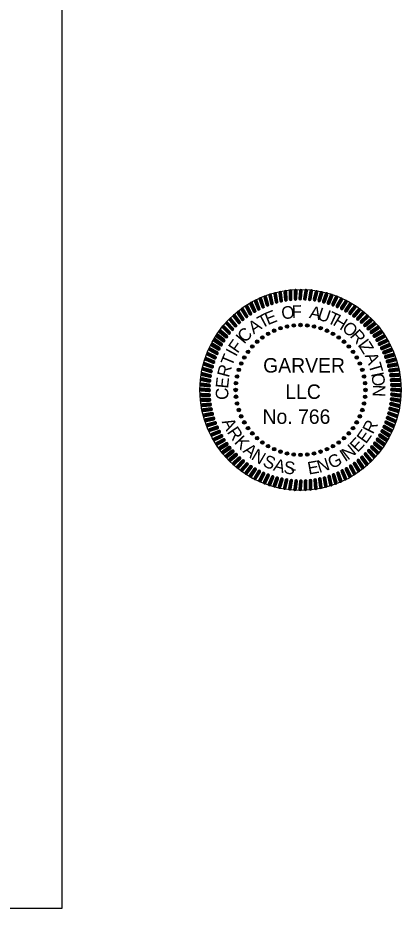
# Model space of a CAD drawing. Extents: x 0 to 19, y -0.6 to 11.3.
# Drawn here: x 16.74 to 19.02, y 0 to 5.31 of the extents above; entities that cross this region are included whole.
import ezdxf

# ---------------------------------------------------------------- set-up
doc = ezdxf.new("R2010")
doc.units = 0
for name, color, linetype in [('G-ANNO-STMP', 7, 'Continuous'), ('G-ANNO-TEXT', 7, 'Continuous'), ('G-Border-Paper', 7, 'Continuous'), ('G-No Plot-Stamp-1', 7, 'Continuous'), ('G-No Plot-Stamp-2', 7, 'Continuous')]:
    doc.layers.add(name, color=color, linetype=linetype)

# ---------------------------------------------------------------- blocks, each defined once
blk = doc.blocks.new('SEALDO')
at = {"layer": 'G-ANNO-TEXT'}
for radius in [0.0396, 0.0305, 0.0213, 0.0122, 0.00305]:
    blk.add_circle((1.403, -0.456), radius, dxfattribs=at)
blk = doc.blocks.new('SEALRI')
at = {"layer": 'G-ANNO-TEXT'}
for p, q in [((-0.023, 2.258), (-0.038, 2.081)), ((-0.008, 2.281), (-0.028, 2.056)), ((0.004, 2.286), (-0.016, 2.049)), ((0.016, 2.285), (-0.004, 2.048)), ((0.028, 2.278), (0.008, 2.052)), ((0.023, 2.076), (0.038, 2.253))]:
    blk.add_line(p, q, dxfattribs=at)
for centre, start, end in [((0.008, 2.256), 355, 175), ((-0.008, 2.078), 175, 355)]:
    blk.add_arc(centre, 0.0305, start, end, dxfattribs=at)

msp = doc.modelspace()

# ---------------------------------------------------------------- linework, layer by layer
at = {"layer": 'G-Border-Paper'}
msp.add_lwpolyline([(17, 11), (0, 11), (0, 0), (17, 0)], close=True, dxfattribs=at)
at = {"layer": 'G-No Plot-Stamp-1'}
msp.add_circle((18.4222, 3.0925), 0.6, dxfattribs=at)
at = {"layer": 'G-No Plot-Stamp-2'}
msp.add_circle((18.4222, 3.0925), 0.6, dxfattribs=at)

# ---------------------------------------------------------------- block references
at = {"layer": 'G-ANNO-STMP'}
for name, xscale, yscale, rotation in [('SEALRI', 0.2624620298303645, 0.26246202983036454, 18), ('SEALRI', 0.2624620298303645, 0.2624620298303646, 15.000000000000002), ('SEALRI', 0.2624620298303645, 0.2624620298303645, 12.000000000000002), ('SEALRI', 0.2624620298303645, 0.2624620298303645, 9), ('SEALRI', 0.2624620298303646, 0.26246202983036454, 6), ('SEALRI', 0.2624620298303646, 0.2624620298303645, 3.0000000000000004), ('SEALRI', 0.26246202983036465, 0.2624620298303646, -2.9999999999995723), ('SEALRI', 0.2624620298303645, 0.2624620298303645, -5.9999999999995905), ('SEALRI', 0.2624620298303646, 0.26246202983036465, -8.999999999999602), ('SEALRI', 0.2624620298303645, 0.26246202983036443, -11.999999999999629), ('SEALRI', 0.2624620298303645, 0.2624620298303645, -14.999999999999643), ('SEALRI', 0.26246202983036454, 0.2624620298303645, -17.99999999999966), ('SEALRI', 0.2624620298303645, 0.2624620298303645, 30.00000000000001), ('SEALRI', 0.2624620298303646, 0.26246202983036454, 26.99999999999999), ('SEALRI', 0.26246202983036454, 0.26246202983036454, 23.99999999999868), ('SEALRI', 0.26246202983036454, 0.26246202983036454, 20.999999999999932), ('SEALRI', 0.2624620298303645, 0.26246202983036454, -20.999999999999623), ('SEALRI', 0.2624620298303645, 0.26246202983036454, -23.999999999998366), ('SEALRI', 0.26246202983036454, 0.26246202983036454, -26.999999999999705), ('SEALRI', 0.26246202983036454, 0.2624620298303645, -29.99999999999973), ('SEALRI', 0.26246202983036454, 0.26246202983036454, 38.999999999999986), ('SEALRI', 0.2624620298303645, 0.2624620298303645, 36), ('SEALRI', 0.2624620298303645, 0.26246202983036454, 33), ('SEALRI', 0.26246202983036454, 0.2624620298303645, -32.999999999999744), ('SEALRI', 0.2624620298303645, 0.2624620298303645, -35.999999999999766), ('SEALRI', 0.26246202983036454, 0.2624620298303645, -38.999999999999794), ('SEALRI', 0.26246202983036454, 0.2624620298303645, 44.999999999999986), ('SEALRI', 0.26246202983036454, 0.2624620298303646, 41.999999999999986), ('SEALRI', 0.26246202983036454, 0.2624620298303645, -41.99999999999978), ('SEALRI', 0.26246202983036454, 0.2624620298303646, -44.999999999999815), ('SEALRI', 0.26246202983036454, 0.26246202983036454, 50.99999999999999), ('SEALRI', 0.2624620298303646, 0.26246202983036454, 47.99999999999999), ('SEALDO', 0.2624620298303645, 0.26246202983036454, 131.99999999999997), ('SEALDO', 0.2624620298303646, 0.26246202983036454, 125.99999999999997), ('SEALDO', 0.2624620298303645, 0.26246202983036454, 119.99999999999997), ('SEALDO', 0.2624620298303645, 0.26246202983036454, 113.99999999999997), ('SEALDO', 0.26246202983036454, 0.2624620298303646, 107.99999999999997), ('SEALDO', 0.26246202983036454, 0.26246202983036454, 101.99999999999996), ('SEALDO', 0.2624620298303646, 0.2624620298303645, 95.99999999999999), ('SEALDO', 0.26246202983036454, 0.26246202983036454, 90), ('SEALDO', 0.2624620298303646, 0.26246202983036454, 83.99999999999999), ('SEALRI', 0.26246202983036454, 0.2624620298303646, -47.99999999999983), ('SEALRI', 0.2624620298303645, 0.26246202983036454, -50.999999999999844), ('SEALRI', 0.2624620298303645, 0.2624620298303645, 59.999999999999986), ('SEALRI', 0.26246202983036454, 0.2624620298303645, 56.99999999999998), ('SEALRI', 0.2624620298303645, 0.2624620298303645, 54), ('SEALDO', 0.2624620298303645, 0.26246202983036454, 144), ('SEALDO', 0.26246202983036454, 0.26246202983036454, 138), ('SEALDO', 0.2624620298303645, 0.26246202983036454, 77.99999999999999), ('SEALDO', 0.2624620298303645, 0.26246202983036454, 72), ('SEALRI', 0.2624620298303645, 0.26246202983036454, -53.99999999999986), ('SEALRI', 0.2624620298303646, 0.26246202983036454, -56.999999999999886), ('SEALRI', 0.2624620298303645, 0.26246202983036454, -59.99999999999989), ('SEALRI', 0.26246202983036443, 0.2624620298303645, 63), ('SEALDO', 0.26246202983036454, 0.2624620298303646, 156.00000000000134), ('SEALDO', 0.26246202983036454, 0.2624620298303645, 150), ('SEALDO', 0.26246202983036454, 0.2624620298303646, 66.00000000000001), ('SEALDO', 0.26246202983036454, 0.2624620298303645, 60.00000000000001), ('SEALRI', 0.2624620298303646, 0.26246202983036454, -62.99999999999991), ('SEALRI', 0.26246202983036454, 0.2624620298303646, 68.99999999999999), ('SEALRI', 0.26246202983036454, 0.2624620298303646, 65.99999999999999), ('SEALDO', 0.26246202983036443, 0.2624620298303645, 168.00000000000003), ('SEALDO', 0.2624620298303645, 0.26246202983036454, 162.00000000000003), ('SEALDO', 0.2624620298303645, 0.2624620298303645, 54), ('SEALDO', 0.26246202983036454, 0.2624620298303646, 48.00000000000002), ('SEALRI', 0.26246202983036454, 0.2624620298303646, -65.99999999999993), ('SEALRI', 0.26246202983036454, 0.26246202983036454, -68.99999999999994), ('SEALRI', 0.2624620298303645, 0.26246202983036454, 75.00000000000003), ('SEALRI', 0.2624620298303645, 0.26246202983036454, 72), ('SEALDO', 0.2624620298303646, 0.2624620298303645, 174.00000000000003), ('SEALDO', 0.2624620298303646, 0.26246202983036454, 42.000000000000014), ('SEALRI', 0.26246202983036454, 0.26246202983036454, -71.99999999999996), ('SEALRI', 0.26246202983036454, 0.2624620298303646, -74.99999999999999), ('SEALRI', 0.2624620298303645, 0.2624620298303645, 81), ('SEALRI', 0.2624620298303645, 0.2624620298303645, 78.00000000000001), ('SEALDO', 0.26246202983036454, 0.26246202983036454, -179.99999999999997), ('SEALDO', 0.2624620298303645, 0.2624620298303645, 36), ('SEALRI', 0.2624620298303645, 0.2624620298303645, -78), ('SEALRI', 0.2624620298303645, 0.2624620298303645, -81.00000000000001), ('SEALRI', 0.2624620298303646, 0.26246202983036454, 84.00000000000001), ('SEALDO', 0.2624620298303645, 0.26246202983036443, -167.99999999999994), ('SEALDO', 0.26246202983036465, 0.26246202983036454, -173.99999999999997), ('SEALDO', 0.26246202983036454, 0.2624620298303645, 29.999999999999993), ('SEALDO', 0.26246202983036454, 0.26246202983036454, 23.99999999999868), ('SEALRI', 0.2624620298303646, 0.2624620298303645, -84.00000000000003), ('SEALRI', 0.26246202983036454, 0.26246202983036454, 90.00000000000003), ('SEALRI', 0.26246202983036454, 0.26246202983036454, 87.00000000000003), ('SEALDO', 0.2624620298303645, 0.26246202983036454, -161.99999999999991), ('SEALDO', 0.2624620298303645, 0.26246202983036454, 18), ('SEALRI', 0.26246202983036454, 0.26246202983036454, -87.00000000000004), ('SEALRI', 0.26246202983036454, 0.26246202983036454, -90.00000000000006), ('SEALRI', 0.2624620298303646, 0.2624620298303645, 93), ('SEALRI', 0.2624620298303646, 0.26246202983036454, 96.00000000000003), ('SEALDO', 0.2624620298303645, 0.26246202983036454, -156.00000000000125), ('SEALDO', 0.2624620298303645, 0.2624620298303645, 12.000000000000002), ('SEALRI', 0.26246202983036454, 0.2624620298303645, -96.0000000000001), ('SEALRI', 0.2624620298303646, 0.26246202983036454, -93.00000000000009), ('SEALRI', 0.26246202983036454, 0.26246202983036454, 99.00000000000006), ('SEALRI', 0.2624620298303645, 0.2624620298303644, 102.00000000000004), ('SEALDO', 0.26246202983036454, 0.26246202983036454, -149.99999999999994), ('SEALDO', 0.2624620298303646, 0.26246202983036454, -143.99999999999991), ('SEALDO', 0.2624620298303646, 0.26246202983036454, 6), ('SEALRI', 0.2624620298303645, 0.2624620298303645, -102.00000000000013), ('SEALRI', 0.26246202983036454, 0.2624620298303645, -99.00000000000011), ('SEALRI', 0.26246202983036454, 0.2624620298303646, 105.00000000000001), ('SEALRI', 0.26246202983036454, 0.26246202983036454, 108.00000000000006), ('SEALDO', 0.26246202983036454, 0.2624620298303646, -137.9999999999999), ('SEALDO', 0.26246202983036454, 0.2624620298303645, -6.000000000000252), ('SEALRI', 0.26246202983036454, 0.2624620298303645, -108.00000000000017), ('SEALRI', 0.26246202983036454, 0.2624620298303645, -105.00000000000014), ('SEALRI', 0.2624620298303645, 0.2624620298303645, 111.00000000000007), ('SEALRI', 0.26246202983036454, 0.26246202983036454, 114.00000000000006), ('SEALDO', 0.26246202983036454, 0.26246202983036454, -131.99999999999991), ('SEALDO', 0.26246202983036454, 0.2624620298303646, -125.9999999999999), ('SEALDO', 0.2624620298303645, 0.26246202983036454, -18.000000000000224), ('SEALDO', 0.2624620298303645, 0.26246202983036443, -12.000000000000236), ('SEALRI', 0.26246202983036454, 0.2624620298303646, -114.0000000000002), ('SEALRI', 0.26246202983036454, 0.26246202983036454, -111.00000000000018), ('SEALRI', 0.26246202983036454, 0.26246202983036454, 117.00000000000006), ('SEALRI', 0.2624620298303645, 0.2624620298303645, 120.00000000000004), ('SEALDO', 0.2624620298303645, 0.26246202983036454, -119.99999999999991), ('SEALDO', 0.26246202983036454, 0.26246202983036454, -113.99999999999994), ('SEALDO', 0.2624620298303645, 0.26246202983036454, -30.00000000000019), ('SEALDO', 0.26246202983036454, 0.2624620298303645, -23.999999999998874), ('SEALRI', 0.26246202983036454, 0.2624620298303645, -120.00000000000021), ('SEALRI', 0.26246202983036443, 0.2624620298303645, -117.00000000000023), ('SEALRI', 0.2624620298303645, 0.2624620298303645, 123.00000000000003), ('SEALRI', 0.26246202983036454, 0.26246202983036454, 126.00000000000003), ('SEALDO', 0.26246202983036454, 0.26246202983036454, -107.99999999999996), ('SEALDO', 0.2624620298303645, 0.26246202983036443, -101.99999999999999), ('SEALDO', 0.2624620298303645, 0.2624620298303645, -42.00000000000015), ('SEALDO', 0.2624620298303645, 0.2624620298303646, -36.00000000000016), ('SEALRI', 0.26246202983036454, 0.2624620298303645, -126.00000000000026), ('SEALRI', 0.2624620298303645, 0.26246202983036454, -123.00000000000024), ('SEALRI', 0.26246202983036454, 0.26246202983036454, 129.00000000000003), ('SEALRI', 0.26246202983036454, 0.2624620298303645, 132), ('SEALRI', 0.2624620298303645, 0.26246202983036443, 135), ('SEALDO', 0.2624620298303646, 0.26246202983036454, -96), ('SEALDO', 0.26246202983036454, 0.26246202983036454, -90.00000000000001), ('SEALDO', 0.2624620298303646, 0.2624620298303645, -84.00000000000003), ('SEALDO', 0.26246202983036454, 0.26246202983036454, -78.00000000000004), ('SEALDO', 0.26246202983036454, 0.2624620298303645, -72.00000000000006), ('SEALDO', 0.2624620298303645, 0.26246202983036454, -66.00000000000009), ('SEALDO', 0.26246202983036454, 0.26246202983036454, -60.0000000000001), ('SEALDO', 0.26246202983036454, 0.26246202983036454, -54.000000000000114), ('SEALDO', 0.26246202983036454, 0.26246202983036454, -48.00000000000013), ('SEALRI', 0.2624620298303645, 0.2624620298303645, -135.00000000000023), ('SEALRI', 0.2624620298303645, 0.26246202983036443, -132.00000000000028), ('SEALRI', 0.2624620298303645, 0.26246202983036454, -129.00000000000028), ('SEALRI', 0.26246202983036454, 0.26246202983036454, 138), ('SEALRI', 0.2624620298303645, 0.26246202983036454, 140.99999999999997), ('SEALRI', 0.2624620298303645, 0.26246202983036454, 144), ('SEALRI', 0.2624620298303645, 0.26246202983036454, -144.00000000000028), ('SEALRI', 0.26246202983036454, 0.2624620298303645, -141.0000000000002), ('SEALRI', 0.26246202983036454, 0.2624620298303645, -138.00000000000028), ('SEALRI', 0.2624620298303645, 0.26246202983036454, 146.99999999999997), ('SEALRI', 0.2624620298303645, 0.26246202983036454, 149.99999999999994), ('SEALRI', 0.2624620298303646, 0.26246202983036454, 152.99999999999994), ('SEALRI', 0.2624620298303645, 0.2624620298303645, 156.00000000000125), ('SEALRI', 0.2624620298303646, 0.2624620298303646, -156.00000000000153), ('SEALRI', 0.2624620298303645, 0.2624620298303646, -153.00000000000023), ('SEALRI', 0.2624620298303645, 0.26246202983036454, -150.00000000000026), ('SEALRI', 0.26246202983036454, 0.2624620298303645, -147.00000000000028), ('SEALRI', 0.2624620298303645, 0.26246202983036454, 159), ('SEALRI', 0.2624620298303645, 0.2624620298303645, 161.99999999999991), ('SEALRI', 0.2624620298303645, 0.26246202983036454, 164.99999999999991), ('SEALRI', 0.2624620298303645, 0.26246202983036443, 167.99999999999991), ('SEALRI', 0.26246202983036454, 0.2624620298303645, 170.9999999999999), ('SEALRI', 0.26246202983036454, 0.2624620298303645, 173.9999999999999), ('SEALRI', 0.2624620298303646, 0.2624620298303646, 176.9999999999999), ('SEALRI', 0.26246202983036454, 0.26246202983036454, 179.99999999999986), ('SEALRI', 0.2624620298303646, 0.26246202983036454, -177.00000000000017), ('SEALRI', 0.2624620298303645, 0.2624620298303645, -174.00000000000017), ('SEALRI', 0.26246202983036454, 0.2624620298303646, -171.00000000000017), ('SEALRI', 0.2624620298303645, 0.2624620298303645, -168.0000000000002), ('SEALRI', 0.2624620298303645, 0.2624620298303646, -165.0000000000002), ('SEALRI', 0.2624620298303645, 0.26246202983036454, -162.00000000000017), ('SEALRI', 0.26246202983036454, 0.26246202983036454, -159.00000000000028)]:
    msp.add_blockref(name, (18.4223, 3.0925), dxfattribs=dict(at, xscale=xscale, yscale=yscale, rotation=rotation))
at = {"layer": 'G-ANNO-STMP', "xscale": 0.26246202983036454, "yscale": 0.26246202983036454}
for name in ['SEALRI', 'SEALDO']:
    msp.add_blockref(name, (18.4223, 3.0925), dxfattribs=at)

# ---------------------------------------------------------------- texts
at = {"layer": 'G-ANNO-STMP'}
for s, rotation, p in [('E', 21.6104, (18.2267, 3.4785)), ('O', 8.2771, (18.3136, 3.5123)), ('F', 1.6104, (18.3705, 3.522)), ('A', 348.2771, (18.4707, 3.5227)), ('U', 341.2772, (18.5176, 3.5152)), ('T', 334.9438, (18.5765, 3.4962)), ('T', 28.2771, (18.1905, 3.4573)), ('H', 328.2771, (18.6103, 3.4828)), ('C', 44.3881, (18.0896, 3.3699)), ('A', 34.9438, (18.1428, 3.4228)), ('O', 319.7874, (18.6645, 3.452)), ('R', 311.9933, (18.7137, 3.4128)), ('I', 49.7408, (18.0858, 3.3622)), ('F', 54.9438, (18.0468, 3.3073)), ('I', 307.0081, (18.7595, 3.3613)), ('Z', 301.6104, (18.7683, 3.3523)), ('T', 67.4314, (18.0126, 3.2289)), ('I', 61.6104, (18.0378, 3.2871)), ('A', 292.9752, (18.8037, 3.2978)), ('R', 74.9438, (17.9951, 3.1629)), ('T', 286.3085, (18.8272, 3.2435)), ('I', 281.6104, (18.8422, 3.1908)), ('O', 276.4823, (18.8451, 3.1881)), ('E', 83.8985, (17.9897, 3.0987)), ('C', 91.8842, (17.993, 3.0347)), ('N', 268.2771, (18.8545, 3.1248)), ('A', 296.5747, (17.9514, 2.9025)), ('R', 304.6183, (17.981, 2.8408)), ('R', 63.0959, (18.8543, 2.8247)), ('K', 313.3805, (18.0231, 2.778)), ('E', 54.7309, (18.8126, 2.7672)), ('A', 321.2584, (18.0738, 2.7232)), ('N', 38.9821, (18.705, 2.6701)), ('E', 46.6807, (18.7629, 2.7159)), ('N', 329.1099, (18.1231, 2.6817)), ('G', 26.4132, (18.608, 2.6194)), ('I', 32.979, (18.6876, 2.6612)), ('S', 337.6294, (18.1923, 2.6396)), ('A', 345.4073, (18.2555, 2.613)), ('S', 352.8046, (18.3191, 2.5952)), ('E', 10.0695, (18.4713, 2.5871)), ('N', 17.8686, (18.5341, 2.5965)), ('-', 0.8385, (18.3644, 2.5854))]:
    msp.add_text(s, height=0.075, rotation=rotation, dxfattribs=at).set_placement(p)
for s, p in [('GARVER', (18.1993, 3.1961)), ('LLC', (18.3314, 3.039)), ('No. 766', (18.1956, 2.8903))]:
    msp.add_text(s, height=0.0864, dxfattribs=at).set_placement(p)

doc.saveas('drawing.dxf')
